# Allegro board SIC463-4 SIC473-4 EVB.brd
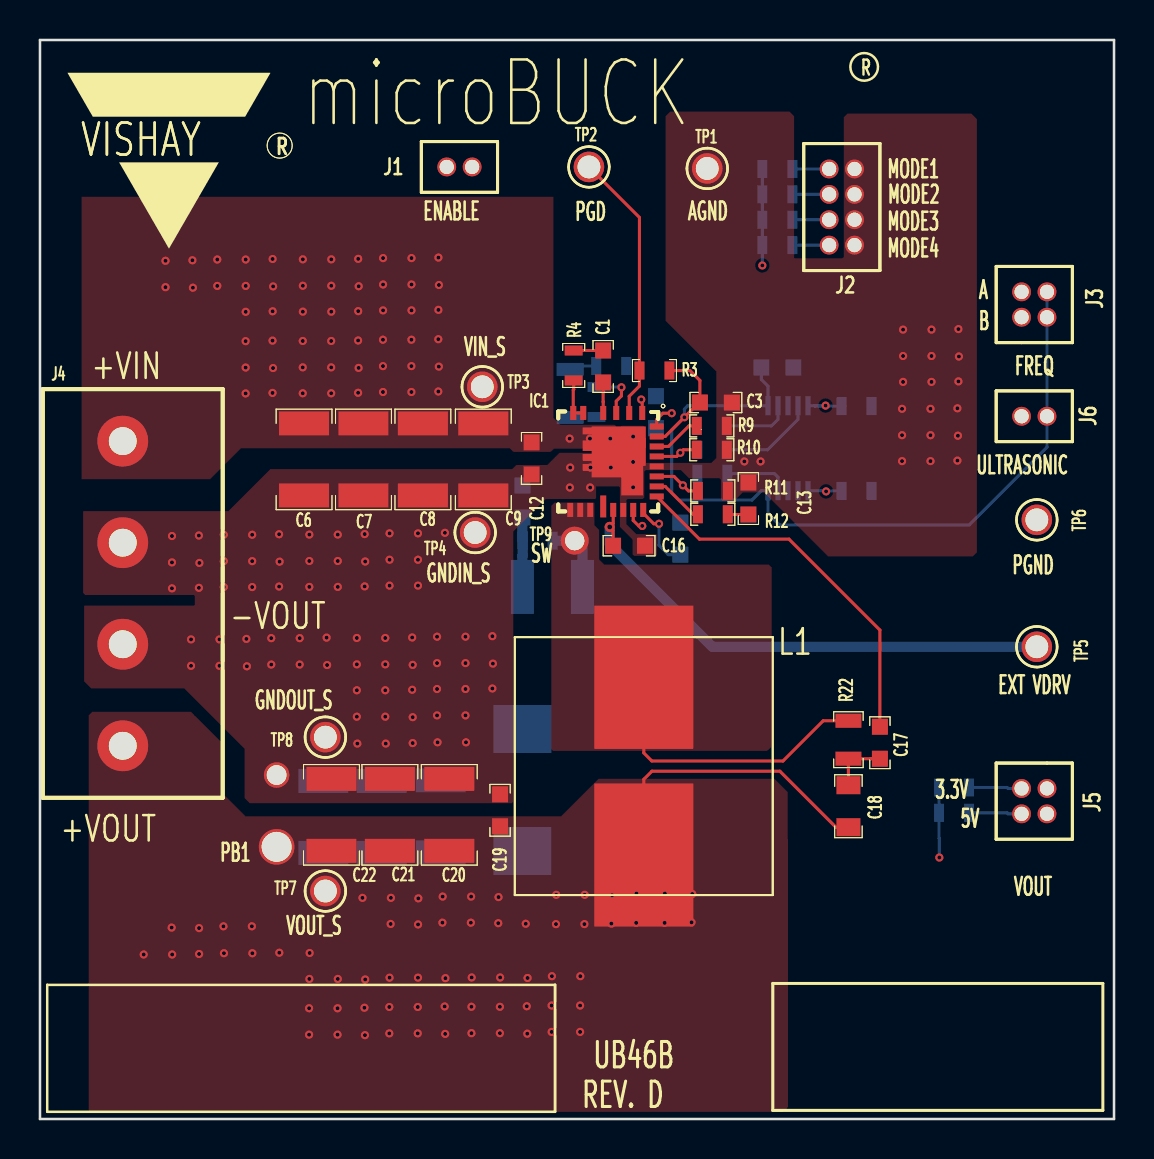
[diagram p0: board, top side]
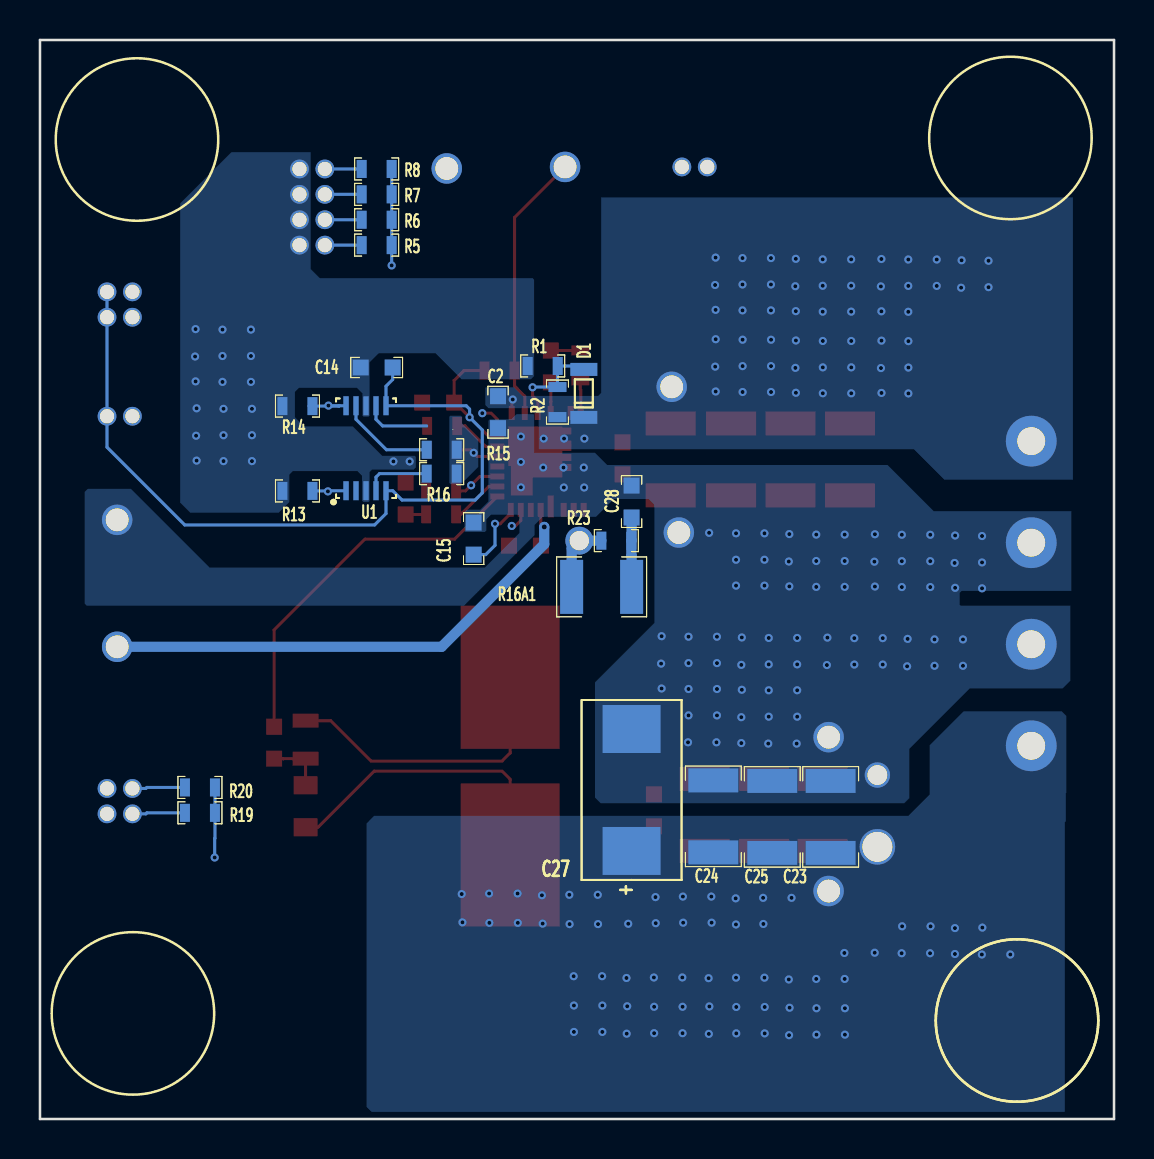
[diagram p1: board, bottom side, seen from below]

Outline 53.72 x 53.97 mm; copper layers: TOP, LAYER2, LAYER3, BOTTOM. Coordinates in mm from the lower left corner of the outline.
Outline path: 33.07,34.49 33.07,34.49 ; 0,53.97 0,0 53.72,0 53.72,53.97 0,53.97

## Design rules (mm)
constraint set DEFAULT: min track width 0.1

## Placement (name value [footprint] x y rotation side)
C1  100n  [C0603-TDK]  28.17 37.64 270 top
C2  0.1uF  [C0603-TDK]  30.81 35.36 270 bottom
C3  1u  [C0603-TDK]  33.81 35.84 0 top
C6  2.2uF  [C1210-TDK]  13.21 32.99 90 top
C7  2.2uF  [C1210-TDK]  16.18 32.99 90 top
C8  2.2uF  [C1210-TDK]  19.15 32.99 90 top
C9  2.2uF  [C1210-TDK]  22.17 32.99 90 top
C12  0.1uF  [C0603-TDK]  24.59 33.05 270 top
C13  1n  [C0603-TDK]  35.43 31.04 90 top
C14  1uF  [C0603-TDK]  36.88 37.59 180 bottom
C15  33nF  [C0603-TDK]  32.03 29.03 270 bottom
C16  4.7uF  [C0603-TDK]  29.46 28.68 0 top
C17  2.2nF  [C0603-TDK]  42.01 18.82 270 top
C18  560p  [C0805-TDK]  40.44 15.65 270 top
C19  0.1uF  [C0603-TDK]  23.01 15.44 270 top
C20  22uF  [C1210-TDK]  20.47 15.21 270 top
C21  22uF  [C1210-TDK]  17.5 15.21 270 top
C22  22uF  [C1210-TDK]  14.58 15.21 270 top
C23  22uF  [C1210-TDK]  14.17 15.11 270 bottom
C24  22uF  [C1210-TDK]  20.04 15.14 270 bottom
C25  22uF  [C1210-TDK]  17.09 15.11 270 bottom
C27  100uF 20V  [D3L]  24.13 16.46 90 bottom
C28  DNP  [C0603-TDK]  24.13 30.89 90 bottom
D1  8.2V  [SOD323]  26.52 36.3 90 bottom
IC1  SiC46X  [SIC471]  28.42 32.89 270 top
J1  HEADER2x1  [MINIJUMPER2]  20.35 47.62 0 top
J2  HEADER 4X2  [MINIJUMPER2X4]  40.74 43.71 180 top
J3  HEADER 2X2  [MINIJUMPER2X2]  50.37 41.38 270 top
J4  CON4  [ED120-4DS2]  4.14 33.91 270 top
J5  HEADER 2X2  [MINIJUMPER2X2]  49.1 15.27 90 top
J6  JUMPER  [MINIJUMPER2]  49.1 35.15 0 top
L1  15uH  [IHLP]  30.2 17.65 270 top
NOREF  -  []  -6.43 45.75 0 top
NOREF#2  -  []  6.45 43.54 0 top
PB1  CON2  [2PROBE]  11.84 13.61 135 top
R1  10K  [R0603-VISHAY]  28.57 37.67 180 bottom
R2  DNP  [R0603-VISHAY]  27.84 35.86 90 bottom
R3  102K  [R0603-VISHAY]  30.73 37.44 180 top
R4  3.3  [R0603-VISHAY]  26.7 37.69 270 top
R5  2K  [R0603-VISHAY]  36.88 43.71 0 bottom
R6  301K  [R0603-VISHAY]  36.88 44.98 0 bottom
R7  499K  [R0603-VISHAY]  36.88 46.25 0 bottom
R8  1M  [R0603-VISHAY]  36.88 47.52 0 bottom
R9  47k  [R0603-VISHAY]  33.6 34.67 180 top
R10  DNP  [R0603-VISHAY]  33.6 33.48 180 top
R11  10K  [R0603-VISHAY]  33.66 31.42 180 top
R12  56k  [R0603-VISHAY]  33.66 30.25 180 top
R13  100k  [R0603-VISHAY]  40.84 31.42 180 bottom
R14  100k  [R0603-VISHAY]  40.84 35.66 0 bottom
R15  43.2K  [R0603-VISHAY]  33.63 33.48 180 bottom
R16  64.9K  [R0603-VISHAY]  33.63 32.28 0 bottom
R16A1  DNP  [1210]  25.63 26.62 180 bottom
R19  31.6K  [R0603-VISHAY]  45.72 15.32 180 bottom
R20  52.3K  [R0603-VISHAY]  45.72 16.59 180 bottom
R22  49.9K  [R0805-VISHAY]  40.44 18.97 90 top
R23  DNP  [R0603-VISHAY]  24.89 28.93 180 bottom
TP1  CON1  [TP30]  33.38 47.55 0 top
TP2  CON1  [TP30]  27.46 47.62 0 top
TP3  CON1  [TP30]  22.12 36.63 0 top
TP4  CON1  [TP30]  21.77 29.34 0 top
TP5  CON1  [TP30]  49.86 23.62 0 top
TP6  CON1  [TP30]  49.86 29.97 0 top
TP7  CON1  [TP30]  14.27 11.4 0 top
TP8  CON1  [TP30]  14.27 19.1 0 top
TP9  5002  [TP]  26.75 28.93 0 top
U1  DG2034  [MSOP10]  37.41 33.55 180 bottom

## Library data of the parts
C1 C3 = CAPACITOR NON-POL
C2 C6-C9 C12-C25 C28 = CAP NP
C27 = CAP POL
D1 = DIODE ZENER
IC1 = SiC462W
J1 = CON2: User Part Number: ***
J2 = HEADER 4X2
J3 J5 = HEADER 2X2
J4 = HEADER 4
J6 = JUMPER: User Part Number: ***
L1 = INDUCTOR
PB1 = CON2
R1-R3 R5-R16 R16A1 R19 R20 R22 R23 = RESISTOR
R4 = R
TP1-TP8 = CON1
TP9 = TP_0
U1 = DG2034M

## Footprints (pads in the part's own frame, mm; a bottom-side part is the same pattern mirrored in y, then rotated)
2PROBE
  round 1.778 hole 1.499: 1(0,0)
  round 1.27 hole 0.991: 2(2.54,-2.54)
1210
  rect 1.15x2.7 smd: 1(-1.5,0) 2(1.5,0)
C0603-TDK
  rect 0.8x0.8 smd: 1(-0.8,0) 2(0.8,0)
C0805-TDK
  rect 0.9x1.2 smd: 1(-1.05,0) 2(1.05,0)
C1210-TDK
  rect 1.2x2.5 smd: 1(-1.8,0) 2(1.8,0)
D3L
  rect 2.4x2.9 smd: 1(-3.05,0) 2(3.05,0)
ED120-4DS2
  round 2.54 hole 1.397: 1(0,0) 2(5.08,0) 3(10.16,0) 4(15.24,0)
IHLP
  rect 7.163x4.953 smd: 1(-4.445,0) 2(4.445,0)
MINIJUMPER2
  round 0.94 hole 0.711: 1(0,0) 2(1.27,0)
MINIJUMPER2X2
  round 0.94 hole 0.711: 1(0,0) 2(1.27,0) 3(0,-1.27) 4(1.27,-1.27)
MINIJUMPER2X4
  round 0.94 hole 0.711: 1(0,0) 2(1.27,0) 3(0,-1.27) 4(1.27,-1.27) 5(0,-2.54) 6(1.27,-2.54) 7(0,-3.81) 8(1.27,-3.81)
MSOP10
  rect 0.27x0.95 smd: 1(-1,-2.125) 2(-0.5,-2.125) 3(0,-2.125) 4(0.5,-2.125) 5(1,-2.125) 6(1,2.125) 7(0.5,2.125) 8(0,2.125) 9(-0.5,2.125) 10(-1,2.125)
R0603-VISHAY
  rect 0.5x0.9 smd: 1(-0.75,0) 2(0.75,0)
R0805-VISHAY
  rect 0.7x1.3 smd: 1(-0.95,0) 2(0.95,0)
SIC471
  rect 0.7x0.3 smd: 1(-2.425,1.7) 2(-2.425,1.05) 3(-2.425,0.4) 4(-2.425,-0.25) 5(-2.425,-1.25) 6(-2.425,-1.75) 12(2.425,-1.9) 13(2.425,-1.4) 14(2.425,-0.9) 16(2.425,0.25) 17(2.425,0.75) 18(2.425,1.25) 19(2.425,1.75)
  custom 0.275x0.275 smd: 7(-1.2,0.3)
  round 0 smd: 8(-0.914,-2.54) 10(0.66,-2.565) 11(1.168,-2.515)
  custom 0.5x0.5 smd: 9(-0.2,0.3)
  rect 1.1x0.3 smd: 15(2.25,-0.25)
  rect 0.3x0.7 smd: 20(1.75,2.425) 21(1.25,2.425) 22(0.75,2.425) 23(0.25,2.425) 24(-0.25,2.425) 25(-0.75,2.425) 26(-1.25,2.425) 27(-1.75,2.425)
  rect 3.4x1.1 smd: 28(0,1.2)
SOD323
  rect 0.65x1.35 smd: 1(-1.2,0) 2(1.2,0)
TP
  round 1.397 hole 0.965: 1(0,0)
TP30
  round 1.524 hole 1.143: 1(0,0)

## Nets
GND: C2.2 C3.2 C6.1 C7.1 C8.1 C9.1 C12.2 C13.2 C14.1 C15.1 C16.2 C19.1 C20.1 C21.1 C22.1 C23.1 C24.1 C25.1 C27.2 C28.2 IC1.9 IC1.10 IC1.11 IC1.17 IC1.23 IC1.28 J1.2 J2.1 J2.3 J2.5 J2.7 J4.2 J4.3 PB1.2 R1.1 R9.1 R10.1 R11.1 R13.1 R14.2 TP1.1 TP4.1 TP6.1 TP8.1 U1.3 U1.8
VDD1: C3.1 C14.2 IC1.26 J3.1 J3.2(4) J6.2 R3.1 U1.5 U1.6(V+)
VIN: C2.1 C6.2 C7.2 C8.2 C9.2 C12.1 D1.1(CATHODE) IC1.1 IC1.7 IC1.8 J4.1 R2.1 TP3.1
COMP: IC1.21 R12.2
EN: D1.2 IC1.3 J1.1 R1.2 R2.2
FSW: IC1.24 R10.2 R15.2 R16.1
GL: IC1.15
ILIM: IC1.25 R9.2
PGD: IC1.2 R3.2 TP2.1
VO: C18.2 C19.2 C20.2 C21.2 C22.2 C23.2 C24.2 C25.2 C27.1 J4.4 L1.2 PB1.1 R19.2 R20.2 TP7.1
N9136645: IC1.12 IC1.13 IC1.14 L1.1 R16A1.1 R22.2 R23.1 TP9.1
N9138289: IC1.22 J5.3 J5.4 R11.2
N9138679: C13.1 R12.1
N9140488: C1.1 R4.1
N9140516: C1.2 IC1.4
N9145499: C16.1 IC1.16 TP5.1
N10371426: IC1.5 IC1.6 R4.2
N10441290: IC1.18 J6.1
N10450769: C17.1 IC1.20(VSNS)
N10621393: C17.2 C18.1 R22.1
N10653497: IC1.27 R5.1 R6.1 R7.1 R8.1
N10653505: J2.2 R5.2
N10653567: J2.4 R6.2
N10653613: J2.6 R7.2
N10653671: J2.8 R8.2
N16777534: J5.2(4) R20.1
N16796780: C28.1 R16A1.2 R23.2
N16799725: J3.3 R13.2 U1.1
N16799736: J3.4 R14.1 U1.10
N16799803: R15.1 U1.9
N16799837: R16.2 U1.4
N16819861: J5.1 R19.1
N1041946515: C15.2 IC1.19

Pads without a net: U1 2 7

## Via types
v1: diameter 0.406, hole 0.203, TOP to BOTTOM, 236 vias
v2: diameter 0.508, hole 0.254, TOP to BOTTOM, 1 via

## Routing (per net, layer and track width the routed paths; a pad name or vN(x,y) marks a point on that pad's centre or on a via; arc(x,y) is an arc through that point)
GND:
  vias: v1(6.6,29.16) v1(6.6,27.84) v1(6.6,26.55) v1(7.56,23.99) v1(7.56,22.67) v1(7.95,29.19) v1(7.97,27.82) v1(7.95,26.57) v1(8.98,23.99) v1(8.98,22.67) v1(9.19,29.23) v1(9.19,27.9) v1(9.19,26.61) v1(10.32,24.02) v1(10.35,22.65) v1(10.61,29.23) v1(10.61,27.9) v1(10.61,26.61) v1(11.57,24.05) v1(11.57,22.73) v1(11.96,29.25) v1(11.99,27.88) v1(11.96,26.63) v1(12.99,24.05) v1(12.99,22.73) v1(13.47,29.23) v1(13.47,27.91) v1(13.47,26.62) v1(14.34,24.08) v1(14.36,22.71) v1(14.89,29.23) v1(14.89,27.91) v1(14.89,26.62) v1(15.85,24.06) v1(15.85,22.74) v1(15.85,21.45) v1(15.85,20.13) v1(15.87,18.78) v1(16.24,29.26) v1(16.27,27.89) v1(16.24,26.64) v1(17.27,24.06) v1(17.27,22.74) v1(17.27,21.45) v1(17.27,20.13) v1(17.3,18.78) v1(17.48,29.3) v1(17.48,27.98) v1(17.48,26.68) v1(18.62,24.09) v1(18.62,21.47) v1(18.64,22.72) v1(18.64,20.1) v1(18.64,18.8) v1(18.91,29.3) v1(18.91,27.98) v1(18.91,26.68) v1(19.86,24.13) v1(19.86,22.81) v1(19.86,21.51) v1(19.86,20.19) v1(19.89,18.84) v1(20.25,29.32) v1(21.28,24.13) v1(21.28,22.81) v1(21.28,21.51) v1(21.28,20.19) v1(21.31,18.84) v1(22.63,24.15) v1(22.65,22.78) v1(22.63,21.54) v1(26.52,32.59) v1(26.5,31.59) v1(27.52,31.59) v1(27.54,32.59) v1(28.55,32.59) v1(29.67,34.14) v1(29.67,32.87) v1(29.67,31.6) v1(35.23,32.89) v1(36.04,32.89) v1(43.12,35.53) v1(43.12,34.2) v1(43.12,32.91) v1(43.17,39.49) v1(43.17,38.17) v1(43.17,36.87) v1(44.59,39.49) v1(44.59,38.17) v1(44.59,36.87) v1(44.54,35.53) v1(44.54,34.2) v1(44.54,32.91) v1(45.89,35.55) v1(45.91,34.18) v1(45.89,32.93) v1(45.94,39.51) v1(45.96,38.14) v1(45.94,36.9)
VDD1: length 46.3
  TOP w0.152: IC1.26 31.27,34.14 v1(32.23,35.1) 32.97,35.84 C3.1 33.01,36.94 32.51,37.44 R3.1
  BOTTOM w0.152: C14.2 36.08,36.99 36.41,36.66 U1.6 32.4,35.68 32.23,35.51 v1(32.23,35.1) 31.6,34.47 31.6,31.32 31.95,30.96 35.61,30.96 36.08,31.43 U1.5 36.41,30.29 36.98,29.72 46.48,29.72 50.37,33.6 J6.2 J3.2 J3.1
VIN: length 0.7
  TOP w0.152: IC1.1 30.12,35.94 v1(30.07,35.99)
  vias: v1(6.28,42.93) v1(6.28,41.61) v1(7.62,42.96) v1(7.65,41.58) v1(8.87,42.99) v1(8.87,41.67) v1(10.29,42.99) v1(10.29,41.67) v1(10.29,40.38) v1(10.28,38.91) v1(10.28,37.59) v1(10.28,36.29) v1(11.64,43.02) v1(11.66,41.65) v1(11.64,40.4) v1(11.63,38.94) v1(11.66,37.56) v1(11.63,36.32) v1(13.15,43) v1(13.15,41.68) v1(13.15,40.39) v1(13.14,38.92) v1(13.14,37.6) v1(13.14,36.3) v1(14.57,43) v1(14.57,41.68) v1(14.57,40.39) v1(14.57,38.92) v1(14.57,37.6) v1(14.57,36.3) v1(15.92,43.03) v1(15.92,40.41) v1(15.91,38.94) v1(15.91,36.33) v1(15.94,41.66) v1(15.94,37.57) v1(17.16,43.07) v1(17.16,41.74) v1(17.16,40.45) v1(17.16,38.98) v1(17.16,37.66) v1(17.16,36.37) v1(18.58,43.07) v1(18.58,41.74) v1(18.58,40.45) v1(18.58,38.98) v1(18.58,37.66) v1(18.58,36.37) v1(19.92,39.01) v1(19.92,36.39) v1(19.93,43.09) v1(19.95,41.72) v1(19.93,40.47) v1(19.95,37.64) v1(26.49,34.04) v1(27.51,34.04) v1(28.52,34.04)
COMP: length 2.6
  TOP w0.152: IC1.21 31.27,31.64 32.66,30.25 R12.2
EN: length 25.4
  TOP w0.152: IC1.3 28.82,35.91 29.08,36.17 v1(29.08,36.6)
  LAYER3 w0.152: v1(29.08,36.6) 26.11,39.57 26.11,48.26 25.28,49.09 20.64,49.09 20.35,48.79 J1.1
  BOTTOM w0.152: v1(29.08,36.6) 29.08,36.61 R2.2 27.84,37.65 R1.2 26.69,37.67 D1.2
FSW: length 2.2
  TOP w0.152: IC1.24 31.85,33.14 v1(32.03,33.32) 32.18,33.48 R10.2
  BOTTOM w0.152: 32.88,32.23 R16.1
ILIM: length 2.4
  TOP w0.152: R9.2 32.46,34.67 31.43,33.64 IC1.25
Net_2: length 3.3
  BOTTOM w0.152: 36.91,35.68 36.91,35 36.59,34.67 34.38,34.67
PGD: length 13.6
  TOP w0.152: TP2.1 29.98,45.1 R3.2 29.98,36.66 29.47,36.15 IC1.2
VO: length 54.3
  TOP w0.152: L1.2 30.2,16.99 30.61,17.4 37.01,17.4 39.81,14.6 C18.2
  LAYER3 w0.152: TP7.1 14.27,9.55 15.98,7.85 39.75,7.85 v1(44.98,13.08)
  BOTTOM w0.152: R20.2 R19.2 44.97,14.05 44.98,14.03 v1(44.98,13.08) 44.96,13.06
  vias: v1(5.19,8.23) v1(6.59,9.58) v1(6.61,8.23) v1(7.96,9.55) v1(7.96,8.25) v1(9.18,9.64) v1(9.2,8.29) v1(10.6,9.64) v1(10.62,8.29) v1(11.97,8.32) v1(13.49,8.31) v1(13.47,7.01) v1(13.46,5.54) v1(13.46,4.22) v1(14.89,7.01) v1(14.88,5.54) v1(14.88,4.22) v1(16.13,11.06) v1(16.27,6.98) v1(16.23,5.57) v1(16.25,4.19) v1(17.48,7.07) v1(17.47,5.6) v1(17.47,4.28) v1(17.55,11.06) v1(17.54,9.76) v1(18.92,11.04) v1(18.91,9.73) v1(18.91,7.07) v1(18.89,5.6) v1(18.89,4.28) v1(20.14,11.13) v1(20.13,9.82) v1(20.28,7.05) v1(20.24,5.63) v1(20.27,4.26) v1(21.56,11.13) v1(21.55,9.82) v1(21.59,7.08) v1(21.58,5.61) v1(21.58,4.29) v1(22.92,9.8) v1(22.94,11.1) v1(23.02,7.08) v1(23,5.61) v1(23,4.29) v1(24.3,9.77) v1(24.39,7.06) v1(24.35,5.64) v1(24.37,4.27) v1(25.61,7.14) v1(25.59,5.68) v1(25.59,4.36) v1(25.82,11.22) v1(25.81,9.75) v1(27.01,5.68) v1(27.01,4.36) v1(27.03,7.14) v1(27.24,11.22) v1(27.23,9.75) v1(28.62,11.19) v1(28.58,9.78) v1(29.82,9.81) v1(29.83,11.28) v1(31.26,11.28) v1(31.24,9.81) v1(32.59,9.84) v1(32.63,11.25)
N9136645: length 18.6
  TOP w0.152: L1.1 30.2,18.31 30.61,17.91 37.16,17.91 39.18,19.92 R22.2
  BOTTOM w0.508: R23.1 TP9.1 27.13,28.55 R16A1.1
N9138289: length 29.7
  TOP w0.152: IC1.22 31.71,32.14 v1(32.16,31.7) 32.44,31.42 R11.2
  LAYER3 w0.152: J5.3 J5.4 50.37,19.18 37.85,31.7 v1(32.16,31.7)
N9138679: length 1
  TOP w0.152: C13.1 34.42,30.24 R12.1
N9140488: length 1.5
  TOP w0.152: R4.1 26.71,38.44 ; 26.71,38.44 C1.1 ; 26.71,38.44 26.7,38.43
N9140516: length 1.5
  TOP w0.152: C1.2 28.17,35.88 28.17,35.87 IC1.4
N9145499: length 26.3
  TOP w0.152: C16.1 28.66,29.45 v2(28.5,29.62) 28.67,29.79 IC1.16
  BOTTOM w0.508: TP5.1 33.63,23.62 28.5,28.75 v2(28.5,29.62)
N10371426: length 2.1
  TOP w0.152: IC1.5 IC1.6 26.67,36.47 26.7,36.49 R4.2
N10441290: length 24
  TOP w0.152: v1(30.12,29.67) 29.95,29.67 29.67,29.94 IC1.18
  LAYER3 w0.152: v1(30.12,29.67) 30.12,30.66 31.62,32.16 47.93,32.16 49.1,33.32 J6.1
N10450769: length 18.8
  TOP w0.152: C17.1 42.01,24.46 37.46,29.01 32.98,29.01 IC1.20
N10621393: length 2.9
  TOP w0.152: C18.1 R22.1 41.55,18.02 41.55,18.02 C17.2
N10653497: length 16.5
  TOP w0.152: v1(31.6,35.31) 31.16,35.31 30.85,35 IC1.27
  LAYER3 w0.152: v1(36.13,42.7) 34.26,42.7 31.6,40.03 v1(31.6,35.31) 31.57,35.28
  BOTTOM w0.152: R8.1 R7.1 R6.1 R5.1 v1(36.13,42.7)
N10653505: length 1.8
  BOTTOM w0.152: J2.2 R5.2
N10653567: length 1.8
  BOTTOM w0.152: J2.4 R6.2
N10653613: length 1.8
  BOTTOM w0.152: J2.6 R7.2
N10653671: length 1.8
  BOTTOM w0.152: J2.8 R8.2
N16777534: length 2.6
  BOTTOM w0.152: J5.2 48.43,16.54 48.37,16.59 R20.1
N16796780: length 3.5
  BOTTOM w0.508: R16A1.2 24.13,28.17 24.14,28.19 R23.2 24.13,28.94 C28.1
N16799725: length 28.5
  LAYER3 w0.152: v1(39.32,31.39) 50.06,31.39 52.12,33.45 52.12,42.32 51.84,42.6 49.4,42.6 49.1,42.29 J3.3
  BOTTOM w0.152: 39.29,31.42 R13.2 ; 39.29,31.42 39.29,31.43 U1.1 ; 39.29,31.42 39.27,31.39 ; 39.29,31.42 v1(39.32,31.39)
N16799736: length 14.6
  LAYER3 w0.152: J3.4 42.7,40.11 39.29,36.7 v1(39.29,35.69)
  BOTTOM w0.152: 38.75,35.68 39.29,35.68 v1(39.29,35.69) ; 38.75,35.68 38.77,35.66 R14.1 40.27,35.66 ; 38.75,35.68 U1.10
N16799803: length 4.8
  BOTTOM w0.152: R15.1 36.39,33.48 37.91,35 U1.9
N16799837: length 3.3
  BOTTOM w0.152: R16.2 36.74,32.28 36.91,32.11 U1.4
N16819861: length 2.6
  BOTTOM w0.152: J5.1 48.43,15.27 48.37,15.32 R19.1
N1041946515: length 3.5
  TOP w0.152: v1(30.96,29.78) 30.7,29.78 30.17,30.3 IC1.19
  BOTTOM w0.152: C15.2 31.43,28.23 30.96,28.7 v1(30.96,29.78)

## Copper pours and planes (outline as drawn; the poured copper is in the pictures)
GND on TOP: outline of 82 points within 2.16,15.8 46.86,50.39
GND on BOTTOM: 37.54,30.86 37.62,30.94 37.62,32.18 37.85,32.41 41.07,32.41 41.25,32.23 41.25,30.86 41.78,30.33 46.2,30.33 46.71,30.84 46.71,45.8 44.15,48.36 40.18,48.36 40.18,42.52 39.73,42.06 29.08,42.06 29.01,41.99 29.01,37.16 29.16,37.01 32.64,37.01 33.93,38.3 36.78,38.3 37.24,37.85 37.24,35.18 37.29,35.13 37.54,35.13 37.59,35.18 37.59,36.3 37.87,36.58 40.77,36.58 40.97,36.37 40.97,35.1 40.51,34.65 38.07,34.65 36.6,33.17 34.98,33.17 34.92,33.12 34.92,32.59 35.03,32.49 37.11,32.49 37.24,32.36 37.24,30.91 37.29,30.86
GND on BOTTOM: 25.35,32.71 25.96,33.32 28.98,33.32 29.01,33.35 29.01,35.23 29.03,35.25 29.89,35.25 30.15,35 31.22,35 31.29,34.92 31.29,30.89 31.7,30.48 32.36,30.48 32.49,30.35 32.49,29.41 32.43,29.36 31.47,29.36 31.39,29.44 31.39,30 31.16,30.23 29.79,30.23 29.74,30.17 29.74,29.31 31.47,27.58 45.24,27.58 49.17,31.52 51.33,31.52 51.48,31.37 51.48,25.78 51.38,25.68 32.51,25.68 28.98,29.21 28.98,29.72 28.57,30.12 25.91,30.12 25.02,31.01 23.27,31.01 22.99,30.73 22.99,24.82 25.96,21.84 25.96,16.08 25.68,15.8 23.6,15.8 20.78,15.8 10.49,15.8 10.24,16.05 10.24,18.52 7.21,21.54 2.57,21.54 2.18,21.92 2.18,25.68 7.67,25.68 7.72,25.73 7.72,26.31 7.62,26.42 2.13,26.42 2.13,30.4 9.02,30.4 11.33,32.71
GND on LAYER2: 0.56,0.3 39.52,0.3 39.57,0.35 39.57,26.66 39.49,26.74 30.4,26.74 29.05,28.08 29.05,34.79 28.54,35.3 26.64,35.3 17.34,44.59 17.34,53.39 0.56,53.39
GND on LAYER2: 53.08,0.42 53.08,53.42 17.75,53.42 17.75,44.52 26.59,35.68 28.67,35.68 29.31,35.04 29.31,28.31 30.73,26.89 39.49,26.89 39.74,26.64 39.74,0.37 39.82,0.3 52.95,0.3
GND on LAYER3: 29.03,34.62 29.08,34.67 32.11,34.67 32.77,35.33 32.77,38.46 31.29,39.93 31.29,50.16 31.52,50.39 37.49,50.39 37.72,50.16 37.72,43.1 37.82,43 40.16,43 40.21,43.05 40.21,50.11 40.39,50.29 46.58,50.29 46.86,50.01 46.86,33.05 46.84,33.05 46.18,32.38 31.01,32.38 29.64,31.01 26.31,31.01 25.45,30.15 25.45,28.17 27.28,26.34 42.27,26.34 43.56,25.04 43.56,15.93 43.43,15.8 10.49,15.8 10.24,16.05 10.24,18.49 7.21,21.51 2.59,21.51 2.18,21.92 2.18,25.68 7.7,25.68 7.75,25.73 7.75,26.31 7.65,26.42 2.11,26.42 2.11,30.96 8.46,30.96 10.67,33.17 28.96,33.17 29.03,33.25
VIN on TOP: 23.67,33.38 25.55,33.38 25.7,33.53 28.78,33.53 28.8,33.55 28.8,34.67 28.75,34.72 26.03,34.72 25.68,35.08 25.68,46.13 2.08,46.13 2.08,32 8.51,32 10.06,33.55 23.49,33.55
VIN on BOTTOM: 28.75,33.5 28.78,33.53 28.78,35.48 28.85,35.56 31.29,35.56 31.44,35.71 31.44,36.58 31.42,36.6 30,36.6 29.56,36.17 25.81,36.17 25.65,36.32 25.65,46.1 2.06,46.1 2.06,31.98 8.48,31.98 10.01,33.5
VIN on LAYER3: 28.78,33.5 28.8,33.53 28.8,35.69 25.68,38.81 25.68,46.1 2.11,46.1 2.11,31.98 8.51,31.98 10.03,33.5
FSW on BOTTOM: 32.66,35.18 33.2,35.18 33.25,35.13 33.25,31.83 33.17,31.75 32.66,31.75 31.8,32.61 31.8,33.99 32.61,34.8 32.61,35.13
VO on TOP: 10.29,15.14 9.19,16.23 9.19,18.72 7.54,20.37 2.62,20.37 2.44,20.19 2.44,0.36 37.16,0.36 37.41,0.61 37.41,14 37.4,14.01 37.4,16.34 36.73,17.02 27.94,17.02 26.06,15.14
VO on BOTTOM: 2.46,0.36 37.13,0.36 37.39,0.61 37.39,13.99 37.39,14 37.39,14.78 37.01,15.16 10.29,15.16 9.22,16.23 9.22,18.69 7.52,20.4 2.62,20.4 2.39,20.17 2.39,16.31 2.41,16.28 2.41,14.88 2.46,14.83
VO on LAYER3: 2.41,20.19 2.62,20.4 7.52,20.4 9.25,18.67 9.25,16.18 10.24,15.19 20.35,15.19 21.29,14.25 37.16,14.25 37.41,14 37.41,8.1 16.28,8.1 15.11,9.27 15.11,10.52 15.34,10.74 15.34,11.79 14.83,12.29 13.69,12.29 13.31,11.91 13.31,11 14.02,10.29 14.02,9.25 15.72,7.54 37.41,7.54 37.41,0.61 37.16,0.36 2.41,0.36
N9136645 on TOP: 25.73,30.84 27.71,30.84 27.74,30.81 27.74,29.69 27.97,29.46 27.97,27.99 28.22,27.74 36.45,27.74 36.6,27.58 36.6,18.64 36.37,18.41 25.65,18.41 25.58,18.49 25.58,30.68

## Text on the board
Ref Des/Silkscreen Top: R | PB1 | GNDOUT_S | VOUT_S | ENABLE | GNDIN_S | VIN_S | SW | PGD | AGND | MODE1 | MODE3 | MODE4 | MODE2 | 3.3V | 5V | ULTRASONIC | A | B | EXT VDRV | PGND | VOUT | FREQ | REV. D | UB46B | +VOUT | +VIN | -VOUT | microBUCK
FAB: Layer3 | Layer2 | Bottom | Top | TOTAL THICKNESS - 0.062 -.008/+.005 | 2OZ | 1 THIS IS A 4 LAYER BOARD WITH COMPONENTS ON BOTH SIDES. | 3 SILKSCREEN BOTH SIDES WITH WHITE NON CONDUCTIVE EPOXY BASED INK | 4 IMMERSION GOLD FINISH | 2 SMT LAND PATTERNS THAT HAVE A FINISHED PAD WIDTH RANGING FROM | 6 Material Type: IT175A | 5 GREEN SOLDER MASK | .012 TO .015 MUST USE THE FOLLOWING TOLERANCE, +.002-.0005. | PB VENDOR TO ADJUST ARTWORK TO COMPENSATE FOR ETCH PROCESS. | NOTES: UNLESS OTHERWISE SPECIFIED:
